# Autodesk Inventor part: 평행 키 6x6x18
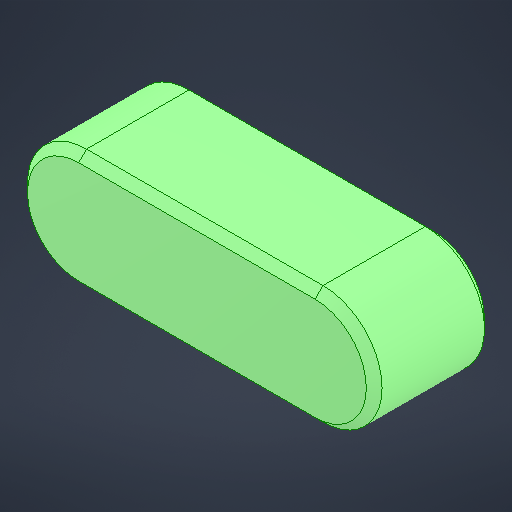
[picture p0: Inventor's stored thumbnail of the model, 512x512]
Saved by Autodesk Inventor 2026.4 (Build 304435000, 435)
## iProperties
Created: 2026-09
Part Number: 평행 키 6x6x18
Material: 강철, 연강
Description: 키 및 해당 키홈
Document SubType Name: Modeling
Designer: user
Density: 7.85 g/cm^3
Appearance: 기본값
Author: jhkim
Sending System: Autodesk Inventor 2027
Preprocessor: ST-DEVELOPER v20.1
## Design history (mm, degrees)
feature "Solid1"
node "솔리드1"
